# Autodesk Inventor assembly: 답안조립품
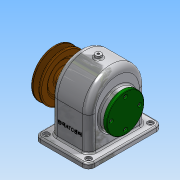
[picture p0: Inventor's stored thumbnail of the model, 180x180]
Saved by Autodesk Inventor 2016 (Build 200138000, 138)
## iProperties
Created: 2018-08
Part Number: 답안조립품
Material: 일반
Document SubType Name: Assembly
Designer: Administrator
Author: Administrator
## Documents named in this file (14)
- C:\Users\Administrator\Desktop\480811V1003\답안조립품.iam
- C:\Users\Administrator\Desktop\480811V1003\본체.ipt
- C:\Users\Administrator\Desktop\480811V1003\축.ipt
- C:\Users\Administrator\Desktop\480811V1003\베어링 6203.ipt
- C:\Users\Administrator\Desktop\480811V1003\키 6x6x22.ipt
- C:\Users\Administrator\Desktop\480811V1003\뒤커버.ipt
- C:\Users\Administrator\Desktop\480811V1003\앞커버.ipt
- C:\Users\Administrator\Desktop\480811V1003\스퍼기어.ipt
- C:\Users\Administrator\Desktop\480811V1003\V-벨트풀리.ipt
- C:\Users\Administrator\Desktop\480811V1003\멈춤나사 M4.ipt
- C:\Users\Administrator\Desktop\480811V1003\볼트 M4.ipt
- C:\Users\Administrator\Desktop\480811V1003\오일 실 28 40 8.ipt
- C:\Users\Administrator\Desktop\480811V1003\키 5x5x18.ipt
- C:\Users\Administrator\Desktop\480811V1003\부시.ipt
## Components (1 placed, 1 different names)
1. V-벨트풀리:1
